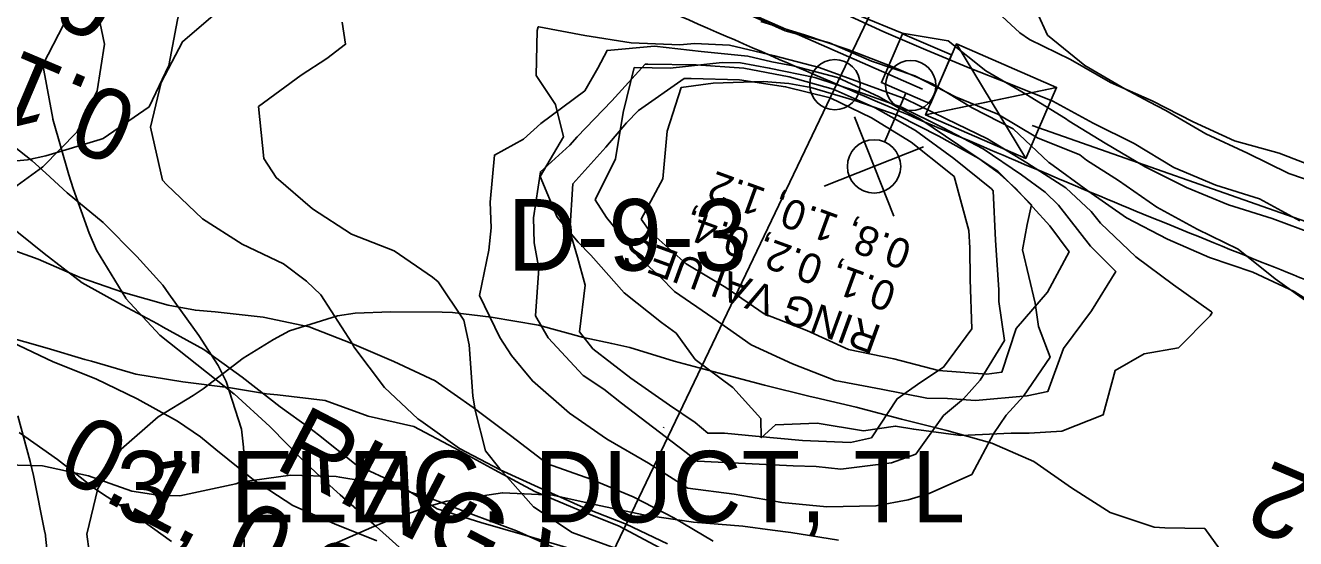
# Model space of a CAD drawing. Extents: x 1638506 to 1658005, y 834807 to 846788.
# Drawn here: x 1639907.1 to 1640119.8, y 842790.3 to 842876.3 of the extents above; entities that cross this region are included whole.
import ezdxf

# ---------------------------------------------------------------- set-up
doc = ezdxf.new("R2010")
doc.units = 0
for name, color, linetype in [('Default', 7, 'Continuous'), ('Old_Level_1', 7, 'Continuous'), ('Old_Level_2', 7, 'Continuous'), ('Scratch_Level_0', 7, 'Continuous')]:
    doc.layers.add(name, color=color, linetype=linetype)

msp = doc.modelspace()

# ---------------------------------------------------------------- linework, layer by layer
at = {"layer": 'Default'}
for p, q in [((1640057.32, 842865.64), (1639806, 842976.14)), ((1640074.6, 842854.03), (1640062.99, 842873.21)), ((1640079.76, 842865.92), (1640057.82, 842861.32)), ((1640054.53, 842864.96), (1640050.96, 842856.75)), ((1640052.48, 842844.35), (1640045.9, 842860.98)), ((1640075.68, 842859.56), (1640311.9, 842776.31)), ((1640057.48, 842855.95), (1640040.86, 842849.39)), ((1640049.18, 842852.65), (1640049.18, 842852.65)), ((1640053.38, 842854.33), (1640053.38, 842854.33)), ((1640013.95, 842808.86), (1640013.99, 842808.95))]:
    msp.add_line(p, q, dxfattribs=at)
for points in [[(1640062.18, 842871.35), (1640058.63, 842863.17), (1640050.42, 842866.74), (1640053.97, 842874.91)], [(1640079.76, 842865.92), (1640062.99, 842873.21), (1640057.82, 842861.32), (1640074.6, 842854.03)], [(1640068.79, 842863.62), (1640057.82, 842861.32), (1640062.99, 842873.21)], [(1640068.79, 842863.62), (1640074.6, 842854.03), (1640079.76, 842865.92)]]:
    msp.add_lwpolyline(points, close=True, dxfattribs=at)
msp.add_circle((1640049.19, 842852.68), 4.47, dxfattribs=at)
at = {"layer": 'Old_Level_1'}
for points in [[(1639901.9, 842853.27), (1639907.42, 842853.8), (1639910.47, 842854.47), (1639919.6, 842857.18), (1639920.08, 842857.33), (1639927.78, 842862.67), (1639931.08, 842869.61), (1639932.55, 842877.22), (1639934.16, 842884.77), (1639934.43, 842892.81), (1639933.89, 842896.44), (1639932.96, 842901.49), (1639929.92, 842907.9), (1639928.62, 842911.21), (1639926.04, 842919.61), (1639925.78, 842920.38), (1639920.81, 842927.62), (1639919.23, 842930.91), (1639915.4, 842935.1), (1639909.14, 842940.26), (1639902.79, 842945.03)], [(1639940.05, 842879.3), (1639933.4, 842873.58), (1639929.78, 842866.75), (1639928.03, 842859.25), (1639930.05, 842850.37)], [(1640123.05, 842841.29), (1640115.86, 842843.92), (1640108.57, 842846.25), (1640101.49, 842849.16), (1640094.6, 842852.6), (1640087.9, 842856.55), (1640081.85, 842860.25), (1640081.27, 842860.71), (1640074.61, 842864.78), (1640067.89, 842868.67), (1640061.58, 842873.7), (1640053.91, 842875), (1640046.82, 842877.89)], [(1640125.87, 842849.03), (1640118.63, 842851.51), (1640111.72, 842854.91), (1640104.76, 842858.14), (1640098.05, 842862.07), (1640095.24, 842863.51), (1640091.21, 842865.66), (1640084.5, 842869.58), (1640078.22, 842874.69), (1640076.52, 842878.47)], [(1640125.02, 842828.25), (1640119.57, 842831.74), (1640112.6, 842834.95), (1640105.36, 842837.43), (1640098.32, 842840.46), (1640091.49, 842844.06), (1640085.01, 842848.6), (1640078.56, 842853.26), (1640078.45, 842853.34), (1640072.49, 842858.95), (1640065.64, 842862.5), (1640058.96, 842866.51), (1640051.91, 842869.51), (1640044.78, 842872.29), (1640037.53, 842874.75), (1640030.21, 842876.98)], [(1639984.9, 842846.69), (1639985.05, 842842.38), (1639984.66, 842838.64), (1639983.09, 842831.07), (1639986.51, 842824.02), (1639988.49, 842820.96), (1639991.99, 842816.72), (1639998.17, 842811.33), (1640004.39, 842807.03), (1640004.68, 842806.85), (1640011.41, 842802.96), (1640018.01, 842798.74), (1640025.78, 842797.73), (1640033.44, 842796.38), (1640033.77, 842796.34), (1640041.3, 842795.63), (1640049.5, 842795.79), (1640054.9, 842796.79), (1640058.4, 842797.86), (1640065.54, 842801.06), (1640069.2, 842807.86), (1640071.32, 842810.99), (1640074.2, 842814.19), (1640078.71, 842820.69), (1640076.73, 842825.85), (1640076.16, 842829.76), (1640074.05, 842838.67), (1640074.81, 842842.96), (1640075.54, 842846.26), (1640069.92, 842851.89), (1640063.37, 842856.25), (1640056.83, 842860.67), (1640053.19, 842862.54), (1640050.02, 842864.33), (1640043.07, 842867.58), (1640035.65, 842869.56), (1640032.07, 842870.23), (1640028.08, 842871.13), (1640020.23, 842871.95), (1640012.41, 842872.82), (1640004.49, 842872.12), (1640002.93, 842869.13), (1640000.75, 842865.34), (1639993.41, 842859.88), (1639990.46, 842857.25), (1639985.62, 842854.57), (1639984.9, 842846.69)], [(1639992.15, 842844.05), (1639992.28, 842839.88), (1639993.07, 842835.58), (1639992.47, 842827.65), (1639994.61, 842823.92), (1640000.47, 842817.64), (1640003.93, 842815.34), (1640006.91, 842812.98), (1640013.28, 842808.12), (1640019.65, 842803.25), (1640027.66, 842802.89), (1640035.67, 842802.52), (1640039.47, 842802.4), (1640043.6, 842801.94), (1640052.12, 842802.99), (1640056.16, 842804.47), (1640060.8, 842810.92), (1640064.17, 842813.72), (1640066.94, 842816.83), (1640071.01, 842823.49), (1640070.11, 842830.05), (1640070.07, 842831.97), (1640069.51, 842840.32), (1640069.16, 842848.59), (1640068.84, 842848.91), (1640062.54, 842853.98), (1640056.12, 842858.7), (1640049.35, 842862.47), (1640042.36, 842865.65), (1640034.97, 842867.7), (1640027.36, 842869.17), (1640019.41, 842869.68), (1640011.33, 842869.84), (1640010.87, 842869.8), (1640005.29, 842863.69), (1639999.5, 842857.66), (1639998.23, 842856.21), (1639993.32, 842851.77), (1639992.15, 842844.05)], [(1639998.26, 842841.83), (1639999.55, 842837.47), (1640000.79, 842832.77), (1639999.89, 842824.95), (1640002.09, 842822.11), (1640008.44, 842817.18), (1640014.95, 842812.69), (1640019.23, 842809.77), (1640021.37, 842807.98), (1640024.17, 842807.97), (1640029.33, 842807.46), (1640037.2, 842806.72), (1640045.23, 842806.41), (1640048.74, 842807.17), (1640053.08, 842813.73), (1640057.05, 842816.54), (1640060.84, 842819.05), (1640065.56, 842825.47), (1640065.3, 842833.71), (1640065.24, 842839.03), (1640065.04, 842841.94), (1640062.63, 842850.96), (1640061.71, 842851.71), (1640055.4, 842856.74), (1640048.74, 842860.81), (1640041.82, 842864.15), (1640034.37, 842866.04), (1640026.65, 842867.2), (1640018.58, 842867.41), (1640017.4, 842867.43), (1640009.76, 842862.07), (1640007.73, 842859.96), (1640004.26, 842855.92), (1639998.77, 842849.78), (1639998.26, 842841.83)], [(1639930.05, 842850.37), (1639930.7, 842849.63), (1639936.75, 842843.88), (1639943.35, 842839.65), (1639950.28, 842836.33), (1639954.16, 842833.46), (1639956.55, 842831.18), (1639961.76, 842823.13), (1639962.07, 842822.44), (1639967.18, 842815.64), (1639972.79, 842810.39), (1639973.28, 842810.04), (1639979.74, 842805.42), (1639986.56, 842801.8), (1639993.56, 842798.66), (1640000.55, 842795.5), (1640007.69, 842792.74), (1640014.62, 842789.43)], [(1639903.92, 842843.16), (1639910.22, 842838.1), (1639916.57, 842833.18), (1639923.34, 842829.41), (1639929.17, 842826.27), (1639930.14, 842825.72), (1639936.93, 842822), (1639943.37, 842817.33), (1639949.71, 842812.39), (1639954.73, 842808.83), (1639956.14, 842807.68), (1639962.46, 842802.68), (1639969.42, 842799.43), (1639976.04, 842795.27), (1639983.36, 842793), (1639990.72, 842790.87), (1639998.06, 842788.67)], [(1640022.25, 842789.88), (1640015.64, 842793.8), (1640008.83, 842797.3), (1640001.78, 842800.27), (1639994.52, 842802.81), (1639988.31, 842807.6), (1639982.05, 842812.27), (1639975.7, 842816.76), (1639968.77, 842820), (1639961.74, 842823.02), (1639954.58, 842825.77), (1639946.9, 842827.41), (1639938.87, 842828.28), (1639935.53, 842828.57), (1639930.97, 842829.44), (1639923.52, 842831.56), (1639916.25, 842834.08), (1639909.23, 842837.12), (1639901.99, 842839.7)], [(1640013.29, 842788.77), (1640006.53, 842792.36), (1639999.43, 842795.23), (1639992.36, 842798.18), (1639985.61, 842801.81), (1639978.9, 842805.51), (1639972.12, 842809.08), (1639964.49, 842810.82), (1639957.27, 842813.44), (1639949.27, 842814.38), (1639947.46, 842814.57), (1639941.39, 842815.59), (1639933.42, 842816.58), (1639925.56, 842817.84), (1639918.13, 842820.01), (1639917.05, 842820.31), (1639910.71, 842822.2), (1639903.26, 842824.33)], [(1639904.8, 842823.21), (1639911.74, 842819.91), (1639918.86, 842817.1), (1639925.78, 842813.74), (1639932.55, 842809.98), (1639936.39, 842807.36), (1639938.96, 842805.21), (1639945.25, 842800.14), (1639951.84, 842795.87), (1639958.84, 842792.75), (1639965.95, 842789.92)], [(1639996.29, 842788.5), (1639989.29, 842791.58), (1639982.11, 842794.29), (1639974.94, 842797.03), (1639967.56, 842799.29), (1639959.72, 842800.59), (1639959.13, 842800.69), (1639951.45, 842800.94), (1639943.03, 842799.75), (1639942.32, 842799.47), (1639932.95, 842797.47), (1639929.64, 842797.55), (1639924.87, 842798.26), (1639917.62, 842800.82), (1639909.96, 842802.49), (1639901.62, 842802.7)]]:
    msp.add_lwpolyline(points, dxfattribs=at)
msp.add_circle((1640042.63, 842866.38), 4.21, dxfattribs=at)
at = {"layer": 'Old_Level_2'}
msp.add_line((1640060.26, 842902.7), (1639915.76, 842600.41), dxfattribs=at)
msp.add_open_spline([(1640158.61, 842819.26), (1640157.59, 842819.64), (1640156.58, 842820.02), (1640154.56, 842820.79), (1640153.54, 842821.17), (1640150.51, 842822.33), (1640144.44, 842824.64), (1640130.31, 842830.13), (1640118.24, 842834.94), (1640094.16, 842844.7), (1640078.16, 842851.39), (1640030.3, 842871.79), (1639998.56, 842885.87), (1639966.8, 842899.95)], degree=3, dxfattribs=at)
at = {"layer": 'Scratch_Level_0'}
for points in [[(1639904.44, 842848.57), (1639909.98, 842852.6), (1639915.75, 842858.47), (1639919.09, 842865.36), (1639920.33, 842873.14), (1639918.51, 842881.76), (1639918.41, 842882.27), (1639913.97, 842890.65), (1639912.79, 842892.96), (1639910, 842900.88), (1639909.75, 842902.56), (1639909.93, 842910.79), (1639908.45, 842916.82), (1639907.61, 842920.08), (1639904.31, 842926.64)], [(1640122.45, 842829.46), (1640116.38, 842833.82), (1640110.18, 842838.8), (1640103.29, 842842.15), (1640096.55, 842845.86), (1640090.13, 842850.3), (1640084.76, 842853.75), (1640083.65, 842854.61), (1640076.55, 842857.46), (1640069.92, 842861.42), (1640062.85, 842864.36), (1640056.02, 842867.85), (1640048.77, 842870.33), (1640041.74, 842873.37), (1640034.29, 842875.38), (1640027.31, 842878.51)], [(1640120.51, 842843.56), (1640113.75, 842847.22), (1640106.42, 842849.52), (1640099.37, 842852.5), (1640092.76, 842856.5), (1640085.9, 842859.92), (1640079.14, 842863.59), (1640072.06, 842866.47), (1640064.93, 842869.27), (1640057.87, 842872.19), (1640050.85, 842875.24), (1640043.88, 842878.41)], [(1640124.15, 842852.15), (1640117.01, 842854.91), (1640109.58, 842856.98), (1640102.62, 842860.16), (1640095.79, 842863.65), (1640088.78, 842866.72), (1640082.11, 842870.59), (1640075.22, 842873.93), (1640073.63, 842875.09), (1640069.16, 842879.22)], [(1639913.52, 842876.52), (1639909.98, 842869.71), (1639911.66, 842860.69)], [(1639960.13, 842876.87), (1639960.69, 842873.14), (1639957.56, 842870.79), (1639953.25, 842867.98), (1639946.1, 842862.7), (1639946.99, 842854.02)], [(1639992.94, 842876.08), (1639992.77, 842875.44), (1639992.6, 842867.91), (1639995.83, 842863.08), (1639997.21, 842857.65), (1639993.27, 842851.01), (1639996.12, 842844.16), (1639999.64, 842840), (1640001.74, 842837.82), (1640007.36, 842831.48), (1640013.58, 842826.54), (1640016.07, 842824.72), (1640019.25, 842820.33), (1640025.56, 842815.62), (1640030.22, 842810.41), (1640030.3, 842807.19), (1640032.67, 842809.37), (1640039.65, 842809.65), (1640047.42, 842808.38), (1640052.79, 842809.15), (1640055.83, 842808.62), (1640063.7, 842807.58), (1640072.17, 842807.95), (1640075.19, 842807.95), (1640080.63, 842808.32), (1640087.54, 842811.03), (1640089.57, 842818.48), (1640094.43, 842821.26), (1640100.16, 842822.29), (1640105.45, 842827.65), (1640105.79, 842828.22), (1640105.72, 842828.28), (1640099.33, 842832.81), (1640093.03, 842837.54), (1640087.11, 842843.19), (1640085.57, 842845.1), (1640081.31, 842849.1), (1640074.77, 842853.27), (1640068.17, 842857.31), (1640061.28, 842860.65), (1640054.38, 842863.98), (1640047.2, 842866.63), (1640040, 842869.26), (1640032.51, 842871.19), (1640024.97, 842873), (1640019.13, 842873.28), (1640016.68, 842873.06), (1640008.51, 842873.38), (1640000.73, 842874.62), (1639993.04, 842876.07), (1639992.94, 842876.08)], [(1640002.51, 842847.09), (1640004.41, 842844.12), (1640009.85, 842837.34), (1640013.35, 842834.18), (1640015.78, 842831.73), (1640022.21, 842827.3), (1640028.59, 842822.75), (1640035.56, 842819.59), (1640042.67, 842816.78), (1640050.38, 842815.36), (1640058.04, 842813.81), (1640061.48, 842813.77), (1640066.19, 842813.45), (1640074.84, 842814.25), (1640078.29, 842814.95), (1640080.89, 842822.16), (1640085.59, 842828.47), (1640089.68, 842835.05), (1640085.46, 842839.3), (1640080.07, 842846.18), (1640077.85, 842848.37), (1640073.91, 842851.24), (1640067.47, 842855.64), (1640060.66, 842859.19), (1640053.8, 842862.6), (1640046.58, 842865.17), (1640039.29, 842867.59), (1640031.65, 842869.17), (1640026.85, 842870.01), (1640023.73, 842870.08), (1640015.04, 842869.17), (1640009.04, 842869.25), (1640007.16, 842861.74), (1640005.89, 842853.97), (1640002.51, 842847.09)], [(1640010.2, 842843.83), (1640011.71, 842841.73), (1640017.74, 842836.37), (1640024.35, 842832.36), (1640030.8, 842827.98), (1640037.92, 842825.17), (1640044.89, 842822), (1640052.52, 842820.41), (1640060, 842818.45), (1640068.05, 842817.84), (1640070.6, 842818.21), (1640072.97, 842825.51), (1640078.22, 842831.6), (1640081.84, 842838.37), (1640078.6, 842842.72), (1640072.95, 842848.99), (1640069.8, 842851.79), (1640066.76, 842853.98), (1640060.04, 842857.73), (1640053.21, 842861.22), (1640045.96, 842863.71), (1640038.59, 842865.92), (1640034.9, 842866.59), (1640030.7, 842866.91), (1640022.26, 842866.61), (1640016.89, 842865.92), (1640014.53, 842858.61), (1640013.8, 842850.61), (1640010.2, 842843.83)], [(1639911.66, 842860.69), (1639911.69, 842860.6), (1639914.36, 842851.24), (1639915.06, 842848.96), (1639917.75, 842841.49), (1639919, 842838.66), (1639923.89, 842830.6), (1639923.91, 842830.56), (1639929.56, 842824.37), (1639935.8, 842819.48), (1639941.99, 842814.59), (1639942.02, 842814.57), (1639948.01, 842809.11), (1639953.8, 842803.15), (1639957.49, 842799.7), (1639959.76, 842797.63), (1639965.83, 842792.33), (1639971.84, 842786.91)], [(1639944.12, 842782.34), (1639943.7, 842789.18), (1639943.64, 842791.21), (1639943.97, 842799.66), (1639943.62, 842805.63), (1639943.25, 842808.65), (1639940.71, 842816.63), (1639939.36, 842819.3), (1639936.1, 842824.35), (1639931.11, 842831.34), (1639930.06, 842832.75), (1639925.73, 842837.57), (1639920.08, 842843.29), (1639914.04, 842848.27), (1639910.47, 842851.55), (1639908.21, 842853.63), (1639902.07, 842858.41)], [(1639946.99, 842854.02), (1639949.08, 842850.8), (1639955.16, 842845.54), (1639961.67, 842841.3), (1639968.8, 842838.51), (1639975.25, 842834.14), (1639976.22, 842833.31), (1639980.48, 842826.89), (1639981.41, 842822.8), (1639981.98, 842814.25), (1639982.4, 842811.82), (1639984.14, 842805.02), (1639986.54, 842801.98), (1639992.15, 842795.63), (1639998.64, 842791.32), (1640005.84, 842788.71)], [(1640108.5, 842786.6), (1640104.58, 842791.99), (1640097.91, 842792.09), (1640096.09, 842792.24), (1640088.74, 842794.68), (1640082.26, 842798.82), (1640075.94, 842803.23), (1640068.92, 842806.32), (1640061.39, 842808.41), (1640053.77, 842810.34), (1640046.17, 842812.3), (1640039.29, 842813.92), (1640038.49, 842814.12), (1640030.85, 842816.01), (1640023.28, 842818.03), (1640015.71, 842820.06), (1640008.27, 842822.33), (1640005.27, 842822.97), (1640000.53, 842824.02), (1639992.99, 842826.09), (1639985.06, 842827.42), (1639978.62, 842828.19), (1639976.87, 842828.25), (1639968.28, 842828.31), (1639962.27, 842828.07), (1639959.31, 842827.64), (1639951.32, 842825.13), (1639948.64, 842823.69), (1639943.55, 842820.55), (1639936.83, 842815.42), (1639935.14, 842814.3), (1639929.3, 842810.71), (1639923.09, 842805.31), (1639919.22, 842798.7), (1639917.38, 842791.04), (1639918.52, 842782.31)], [(1639910.36, 842791.26), (1639910.34, 842791.35), (1639908.41, 842800.89), (1639907.88, 842803.22), (1639905.78, 842810.88)], [(1639906.02, 842808.06), (1639912.43, 842803.57), (1639916.25, 842800.58), (1639918.66, 842798.67), (1639925.15, 842794.38), (1639931.53, 842789.84)], [(1640043.21, 842790.01), (1640035.26, 842791.31), (1640032.21, 842791.74), (1640027.21, 842792.39), (1640018.93, 842793.06), (1640010.9, 842794.2), (1640010.87, 842794.2), (1640003.15, 842795.86), (1639995.41, 842797.56), (1639987.04, 842797.96), (1639986.99, 842797.96), (1639977.66, 842796.59), (1639974.69, 842795.75), (1639967.21, 842793.07), (1639965.01, 842792.16), (1639956.09, 842788.26)], [(1639900.56, 842772.52), (1639907.27, 842775.62), (1639911.34, 842782.13), (1639910.36, 842791.26)]]:
    msp.add_lwpolyline(points, dxfattribs=at)
msp.add_circle((1640055.34, 842866.23), 4.21, dxfattribs=at)

# ---------------------------------------------------------------- texts
at = {"layer": 'Default'}
for s, p in [('D-9-3', (1639987.8, 842835.21)), ('3" ELEC. DUCT, TL', (1639922.33, 842793))]:
    msp.add_text(s, height=12, dxfattribs=at).set_placement(p)
at = {"layer": 'Old_Level_1'}
for s, p in [('0.8, 1.0, 1.2', (1640055.8, 842839.93)), ('0.1, 0.2, 0.4,', (1640053.24, 842832.88)), ('RING VALUES', (1640050.67, 842825.83))]:
    msp.add_text(s, height=5, rotation=160, dxfattribs=at).set_placement(p)
at = {"layer": 'Scratch_Level_0'}
for s, rotation, p in [('0.8, 1.0, 1.2', 157.0176, (1639923.93, 842884.33)), ('0.1, 0.2, 0.4,', 157.0176, (1639926.63, 842863.63)), ('RING VALUES', 332.5519, (1639948.51, 842802.25)), ('0.1, 0.2, 0.4,', 332.5519, (1639911.84, 842801.01)), ('0.8, 1.0, 1.2', 157.0176, (1640193.55, 842770.47))]:
    msp.add_text(s, height=12, rotation=rotation, dxfattribs=at).set_placement(p)

doc.saveas('drawing.dxf')
